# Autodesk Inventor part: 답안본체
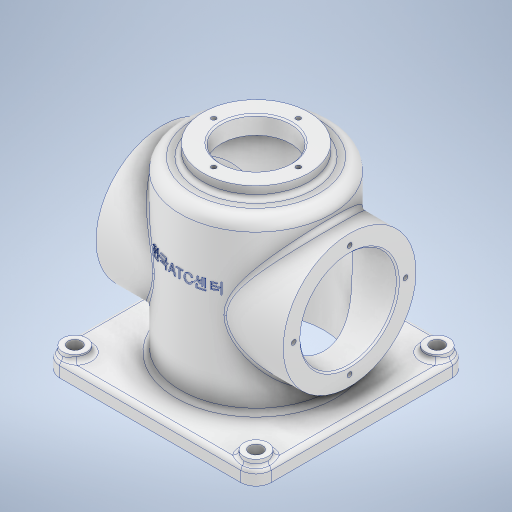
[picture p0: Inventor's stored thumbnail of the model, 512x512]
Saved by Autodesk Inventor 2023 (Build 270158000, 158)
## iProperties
Created: 2025-05
Part Number: 답안본체
Material: 알루미늄 6061
Document SubType Name: Modeling
Designer: ADMIN_PC
Density: 2.7 g/cm^3
Appearance: 알루미늄 - 평지
Mass: 1092.86 g
Surface Area: 1204.83 cm^2
Volume: 404.763 cm^3
Author: ADMIN_PC
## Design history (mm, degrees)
sketch "스케치1"
  geometry: L1 (-70, 70)-(70, 70); L2 (70, 70)-(70, -70); L3 (70, -70)-(-70, -70); L4 (-70, -70)-(-70, 70); L5 (-70, 70)-(70, -70); L6 (70, 70)-(-70, -70); 1 further point
  constraints: 12 end point, 2 midpoint, 2 parallel, 1 horizontal, 1 perpendicular
  dimensions: "d0" = 140 distance of L2.end L3.end; "d1" = 140 distance of L1.end L2.end
extrude "돌출1" new body sketch "스케치1" distance "d2" = 10; taper "d3" = 0 deg
sketch "스케치2"
  geometry: C1 r 50 at (0, 0); 1 further point
  constraints: 1 centre point, 1 coincident
  dimensions: "d4" = 100 diameter of C1
extrude "돌출2" join sketch "스케치2" distance "d5" = 112; taper "d6" = 0 deg
fillet "모깎기1" dims "d10" = 8
fillet "모깎기2" dims "d11" = 3
node "작업 평면1"
sketch "스케치4"
  geometry: L1 (0, 70)-(0, -70) reference; C1 r 44 at (65, 0); 3 further points
  constraints: 2 horizontal alignment, 2 midpoint, 1 centre point
  dimensions: "d13" = 88 diameter of C1; "d14" = 65 distance from line of L1 C1.centre
extrude "돌출4" join sketch "스케치4" distance "d15" = 124; taper "d16" = 0 deg
fillet "모깎기3" dims "d17" = 3
sketch "스케치5"
  geometry: L1 (-70, -65)-(70, -65) reference; C1 r 32 at (0, 0); 2 further points
  constraints: 1 centre point, 1 midpoint, 1 vertical alignment
  dimensions: "d18" = 64 diameter of C1; "d19" = 65 distance from line of L1 C1.centre
extrude "돌출5" cut sketch "스케치5" distance "d20" = 124; taper "d21" = 0 deg
sketch "스케치6" dims "d22" = 74
  geometry: C1 r 32 at (0, 0) reference; 3 further points
  constraints: 2 vertical alignment, 1 coincident, 2 other
hole "구멍1" sketch "스케치6" at (0, 37) diameter "d23" = 3.242; stored, may be unused: countersink angle "d27" = 90 deg, drill point angle "d29" = 118 deg; dims "d24" = 8, "d25" = 4, "d26" = 2, "d28" = 10
sketch "스케치7"
  geometry: C1 r 35 at (0, 0); 1 further point
  constraints: 1 centre point, 1 coincident
  dimensions: "d33" = 70 diameter of C1
extrude "돌출6" join sketch "스케치7" distance "d34" = 8; taper "d35" = 0 deg
sketch "스케치8"
  geometry: C1 r 23 at (0, 0); 1 further point
  constraints: 1 centre point, 1 coincident
  dimensions: "d36" = 46 diameter of C1
extrude "돌출7" cut sketch "스케치8" extent not by distance; stored distance "d37" = 0; taper "d38" = 0 deg
sketch "스케치9"
  geometry: C1 r 35 at (0, 0) reference; C2 r 45 at (0, 0); 1 further point
  constraints: 1 centre point, 1 coincident
  dimensions: "d39" = 90 diameter of C2
extrude "돌출8" cut sketch "스케치9" distance "d40" = 118; taper "d41" = 0 deg
sketch "스케치10" dims "d42" = 56
  geometry: C1 r 23 at (0, 0) reference; 3 further points
  constraints: 2 vertical alignment, 1 coincident, 2 other
hole "구멍2" sketch "스케치10" at (0, 28) diameter "d43" = 3.242; stored, may be unused: countersink angle "d47" = 90 deg, drill point angle "d49" = 118 deg; dims "d44" = 8, "d45" = 4, "d46" = 2, "d48" = 10
fillet "모깎기4" dims "d53" = 3
chamfer "모따기1" distance "d54" = 1; stored, may be unused: second distance "d55" = 2, angle "d56" = 45 deg
fillet "모깎기6" dims "d72" = 3
node "작업 평면2"
sketch "스케치13"
  geometry: L1 (-70, 0)-(70, 0) reference; 2 further points
  constraints: 1 other
  dimensions: "d77" = 80 distance from line of L1 point (-0.204, 80)
feature "엠보싱1" sketch "스케치13" dims "d0" = 140, "d1" = 140, "d78" = 0.5, "d79" = 0
chamfer "모따기3" distance "d80" = 1; stored, may be unused: second distance "d81" = 2, angle "d82" = 45 deg
fillet "모깎기7" dims "d83" = 3
fillet "모깎기9" dims "d85" = 10
sketch "스케치14"
  geometry: L1 (60, -60)-(-60, -60); L2 (-60, -60)-(-60, 60); L3 (-60, 60)-(60, 60); L4 (60, 60)-(60, -60); L5 (60, -60)-(-60, 60); L6 (-60, -60)-(60, 60); C1 r 8 at (-60, -60); C2 r 8 at (-60, 60); C3 r 8 at (60, 60); C4 r 8 at (60, -60); 1 further point
  constraints: 12 end point, 4 centre point, 4 coincident, 2 midpoint, 2 parallel, 1 horizontal, 1 perpendicular
  dimensions: "d86" = 120 distance of L2.end L3.end; "d87" = 120 distance of L1.end L2.end; "d88" = 16 diameter of C1; "d89" = 16 diameter of C2; "d90" = 16 diameter of C3; "d91" = 16 diameter of C4
extrude "돌출11" join sketch "스케치14" distance "d92" = 4; taper "d93" = 0 deg
sketch "스케치16"
  geometry: L1 (60, -60)-(-60, -60); L2 (-60, -60)-(-60, 60); L3 (-60, 60)-(60, 60); L4 (60, 60)-(60, -60); L5 (60, -60)-(-60, 60); L6 (-60, -60)-(60, 60); C1 r 4.5 at (-60, -60); C2 r 4.5 at (-60, 60); C3 r 4.5 at (60, 60); C4 r 4.5 at (60, -60); 1 further point
  constraints: 12 end point, 4 centre point, 4 coincident, 2 midpoint, 2 parallel, 1 horizontal, 1 perpendicular
  dimensions: "d95" = 120 distance of L2.end L3.end; "d96" = 120 distance of L1.end L2.end; "d97" = 9 diameter of C1; "d98" = 9 diameter of C2; "d99" = 9 diameter of C3; "d100" = 9 diameter of C4
extrude "돌출12" cut sketch "스케치16" extent not by distance; stored distance "d101" = 0; taper "d102" = 0 deg
fillet "모깎기10" dims "d103" = 3
node "솔리드1"
pattern_circular "원형 패턴1" dims angle "d31" = 360 deg
mirror "미러1"
pattern_circular "원형 패턴2" dims angle "d51" = 360 deg
feature "A9D066F2-1C7D-4E18-AEED-F7BC21143FA4" dims "d43" = 3.242, "d44" = 8, "d45" = 4, "d46" = 2, "d47" = 90 deg, "d48" = 10, "d49" = 118 deg
other parameters: "d12" = 62
